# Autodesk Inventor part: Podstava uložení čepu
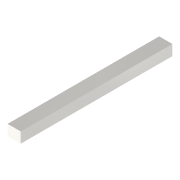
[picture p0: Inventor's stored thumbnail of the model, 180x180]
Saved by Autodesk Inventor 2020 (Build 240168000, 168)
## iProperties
Created: 2025-04
Part Number: Podstava uložení čepu
Material: Ocel
Document SubType Name: Modeling
Designer: doma
Density: 7.85 g/cm^3
Appearance: Ocel
Author: doma
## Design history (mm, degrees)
sketch "Náčrt1"
  geometry: L1 (-5, -4)-(5, -4); L2 (5, -4)-(5, 4); L3 (5, 4)-(-5, 4); L4 (-5, 4)-(-5, -4); L5 (-5, -4)-(5, 4); L6 (5, -4)-(-5, 4); 1 further point
  constraints: 12 end point, 2 midpoint, 2 parallel, 1 horizontal, 1 perpendicular
  dimensions: "d0" = 10 distance of L3.end L2.end; "d1" = 8 distance of L2.end L1.end
extrude "Vysunutí1" new body sketch "Náčrt1" distance "d2" = 115; taper "d3" = 0 deg
node "Těleso1"
